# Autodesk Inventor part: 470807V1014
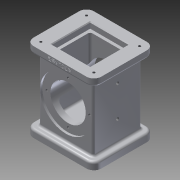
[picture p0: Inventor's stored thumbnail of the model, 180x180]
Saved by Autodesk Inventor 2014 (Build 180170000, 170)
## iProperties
Created: 2017-08
Part Number: 470807V1014
Material: 알루미늄 6061
Document SubType Name: Modeling
Designer: 학생용
Mass: 872.328 g
Surface Area: 642.25 cm^2
Volume: 321.892 cm^3
Density: 2.71 g/cm^3
Appearance: 알루미늄 - 평지
Author: 학생용
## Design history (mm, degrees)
sketch "스케치1"
  geometry: L1 (-36, -41)-(36, -41); L2 (46, -31)-(46, 31); L3 (36, 41)-(-36, 41); L4 (-46, 31)-(-46, -31); L5 (-46, -41)-(46, 41); L6 (46, -41)-(-46, 41); A1 r 10 centre (-36, 31) between (-36, 41) and (-46, 31); A2 r 10 centre (36, 31) between (46, 31) and (36, 41); A3 r 10 centre (36, -31) between (36, -41) and (46, -31); A4 r 10 centre (-36, -31) between (-46, -31) and (-36, -41); 1 further point
  constraints: 12 end point, 8 point on circle, 8 point on line, 8 tangent, 4 centre point, 3 equal radius, 2 midpoint, 2 parallel, 1 horizontal, 1 perpendicular
  dimensions: "d0" = 92 distance of L6.end L5.end; "d1" = 82 distance of L5.end L6.start; "d2" = 10 radius of A1
extrude "돌출1" new body sketch "스케치1" distance "d3" = 10; taper "d4" = 0 deg
node "작업 평면1"
sketch "스케치2"
  geometry: L1 (-36, -41)-(36, -41); L2 (46, -31)-(46, 31); L3 (36, 41)-(-36, 41); L4 (-46, 31)-(-46, -31); L5 (-46, -41)-(46, 41); L6 (46, -41)-(-46, 41); A1 r 10 centre (-36, 31) between (-36, 41) and (-46, 31); A2 r 10 centre (-36, -31) between (-46, -31) and (-36, -41); A3 r 10 centre (36, -31) between (36, -41) and (46, -31); A4 r 10 centre (36, 31) between (46, 31) and (36, 41); 1 further point
  constraints: 12 end point, 8 point on circle, 8 point on line, 8 tangent, 4 centre point, 3 equal radius, 2 midpoint, 2 parallel, 1 horizontal, 1 perpendicular
  dimensions: "d7" = 82 distance of L5.end L6.start; "d8" = 10 radius of A1; "d96" = 92 distance between parallel lines of L2 L4; "d97" = 72 distance of A2.centre A3.centre (derived); "d98" = 62 distance of A4.centre A3.centre (derived)
extrude "돌출2" join sketch "스케치2" distance "d9" = 10; taper "d10" = 0 deg
sketch "스케치3"
  geometry: L1 (-34, -33)-(34, -33); L2 (37, -30)-(37, 30); L3 (34, 33)-(-34, 33); L4 (-37, 30)-(-37, -30); L5 (-37, -33)-(37, 33); L6 (37, -33)-(-37, 33); A1 r 3 centre (-34, 30) between (-34, 33) and (-37, 30); A2 r 3 centre (-34, -30) between (-37, -30) and (-34, -33); A3 r 3 centre (34, -30) between (34, -33) and (37, -30); A4 r 3 centre (34, 30) between (37, 30) and (34, 33); 1 further point
  constraints: 12 end point, 8 point on circle, 8 point on line, 8 tangent, 4 centre point, 3 equal radius, 2 midpoint, 2 parallel, 1 horizontal, 1 perpendicular
  dimensions: "d11" = 74 distance of L6.end L5.end; "d12" = 66 distance of L5.end L6.start; "d31" = 3 radius of A1
extrude "돌출3" join sketch "스케치3" stored distance "d13" = 10; taper "d14" = 0 deg
sketch "스케치4"
  geometry: A1 r 10 centre (36, 31) between (46, 31) and (36, 41) reference; A2 r 10 centre (-36, 31) between (-36, 41) and (-46, 31) reference; A3 r 10 centre (-36, -31) between (-46, -31) and (-36, -41) reference; A4 r 10 centre (36, -31) between (36, -41) and (46, -31) reference; 5 further points
  constraints: 4 coincident
  dimensions: "d15" = 72 distance of point (36, 31) point (-36, 31) (derived); "d16" = 62 distance of point (36, -31) point (36, 31) (derived)
hole "구멍1" sketch "스케치4" at (-36, 31), (36, 31), (36, -31), (-36, -31) diameter "d17" = 3.242; stored, may be unused: countersink angle "d21" = 90 deg, drill point angle "d23" = 118 deg; dims "d18" = 4, "d19" = 4, "d20" = 2, "d22" = 6
sketch "스케치5"
  geometry: A1 r 10 centre (-36, -31) between (-46, -31) and (-36, -41) reference; A2 r 10 centre (36, -31) between (36, -41) and (46, -31) reference; A3 r 10 centre (36, 31) between (46, 31) and (36, 41) reference; A4 r 10 centre (-36, 31) between (-36, 41) and (-46, 31) reference; 5 further points
  constraints: 4 coincident
hole "구멍2" sketch "스케치5" at (36, 31), (36, -31), (-36, -31), (-36, 31) diameter "d24" = 3.242; stored, may be unused: countersink angle "d28" = 90 deg, drill point angle "d30" = 118 deg; dims "d25" = 4, "d26" = 4, "d27" = 2, "d29" = 6
sketch "스케치6"
  geometry: L1 (-21, -24)-(21, -24); L2 (24, -21)-(24, 21); L3 (21, 24)-(-21, 24); L4 (-24, 21)-(-24, -21); L5 (-24, -24)-(24, 24); L6 (24, -24)-(-24, 24); A1 r 3 centre (-21, 21) between (-21, 24) and (-24, 21); A2 r 3 centre (21, -21) between (21, -24) and (24, -21); A3 r 3 centre (21, 21) between (24, 21) and (21, 24); A4 r 3 centre (-21, 21) between (-21, 24) and (-24, 21); A5 r 3 centre (-21, -21) between (-24, -21) and (-21, -24); 3 further points
  constraints: 12 end point, 10 point on circle, 10 point on line, 10 tangent, 5 centre point, 4 equal radius, 3 midpoint, 2 parallel, 2 perpendicular, 1 coincident, 1 horizontal
  dimensions: "d32" = 48 distance of L5.end L6.end; "d33" = 3 radius of A1
extrude "돌출4" cut sketch "스케치6" distance "d34" = 16; taper "d35" = 0 deg
fillet "모깎기2" dims "d37" = 3
sketch "스케치7"
  geometry: L1 (-26, -26)-(26, -26); L2 (26, -26)-(26, 26); L3 (26, 26)-(-26, 26); L4 (-26, 26)-(-26, -26); L5 (-26, -26)-(26, 26); L6 (26, -26)-(-26, 26); 1 further point
  constraints: 12 end point, 2 midpoint, 2 parallel, 2 perpendicular, 1 horizontal
  dimensions: "d38" = 52 distance of L2.end L3.end
extrude "돌출5" cut sketch "스케치7" distance "d39" = 8; taper "d40" = 0 deg
sketch "스케치8"
  geometry: L1 (-19, -22)-(19, -22); L2 (22, -19)-(22, 19); L3 (19, 22)-(-19, 22); L4 (-22, 19)-(-22, -19); L5 (-22, -22)-(22, 22); L6 (22, -22)-(-22, 22); A1 r 3 centre (-19, 19) between (-19, 22) and (-22, 19); A2 r 3 centre (-19, -19) between (-22, -19) and (-19, -22); A3 r 3 centre (19, -19) between (19, -22) and (22, -19); A4 r 3 centre (19, 19) between (22, 19) and (19, 22); 3 further points
  constraints: 12 end point, 8 point on circle, 8 point on line, 8 tangent, 4 centre point, 3 equal radius, 3 midpoint, 2 parallel, 2 perpendicular, 1 coincident, 1 horizontal
  dimensions: "d41" = 44 distance of L5.end L6.end; "d42" = 3 radius of A1
extrude "돌출6" cut sketch "스케치8" distance "d43" = 74; taper "d44" = 0 deg
chamfer "모따기1" distance "d45" = 1; stored, may be unused: second distance "d46" = 2, angle "d47" = 45 deg
sketch "스케치9"
  geometry: L1 (54, 41)-(54, -41); L2 (13, 33)-(95, 33) reference; L3 (98, 36)-(98, 38) reference; L4 (101, 41)-(108, 41) reference; L5 (108, 41)-(108, 27) reference; L6 (108, 27)-(107, 26) reference; L7 (107, 26)-(100, 26) reference; L8 (100, 26)-(100, 22) reference; L9 (100, 22)-(26, 22) reference; L10 (26, 22)-(26, -22) reference; L11 (26, -22)-(100, -22) reference; L12 (100, -22)-(100, -26) reference; L13 (100, -26)-(107, -26) reference; L14 (107, -26)-(108, -27) reference; L15 (108, -27)-(108, -41) reference; L16 (108, -41)-(101, -41) reference; L17 (98, -38)-(98, -36) reference; L18 (95, -33)-(13, -33) reference; L19 (10, -36)-(10, -38) reference; L20 (7, -41)-(0, -41) reference; L21 (0, -41)-(0, -24) reference; L22 (0, -24)-(13, -24) reference; L23 (16, -21)-(16, 21) reference; L24 (13, 24)-(0, 24) reference; L25 (0, 24)-(0, 41) reference; L26 (0, 41)-(7, 41) reference; L27 (10, 38)-(10, 36) reference; L28 (89, -30)-(78, -30); L29 (78, -30)-(78, -22); L30 (78, -22)-(54, -22); L31 (89, -30)-(89, -33); L32 (89, -33)-(54, -33); L33 (54, 22)-(78, 22); L34 (78, 22)-(78, 30); L35 (78, 30)-(89, 30); L36 (89, 30)-(89, 33); L37 (89, 33)-(54, 33); L38 (54, -33)-(54, -22); L39 (54, 22)-(54, 33); L40 (78, -22)-(78, 22); A1 r 3 centre (13, 36) between (10, 36) and (13, 33) reference; A2 r 3 centre (95, 36) between (95, 33) and (98, 36) reference; A3 r 3 centre (101, 38) between (101, 41) and (98, 38) reference; A4 r 3 centre (101, -38) between (98, -38) and (101, -41) reference; A5 r 3 centre (95, -36) between (98, -36) and (95, -33) reference; A6 r 3 centre (13, -36) between (13, -33) and (10, -36) reference; A7 r 3 centre (7, -38) between (7, -41) and (10, -38) reference; A8 r 3 centre (13, -21) between (13, -24) and (16, -21) reference; A9 r 3 centre (13, 21) between (16, 21) and (13, 24) reference; A10 r 3 centre (7, 38) between (10, 38) and (7, 41) reference; 1 further point
  constraints: 28 end point, 7 point on line, 3 perpendicular, 2 horizontal alignment, 2 parallel, 1 collinear, 1 horizontal, 1 midpoint, 1 vertical
  dimensions: "d48" = 54 distance from line of point (0, 0) L1; "d50" = 3 distance of L28.start L31.end; "d51" = 70 diameter of L31 L1; "d52" = 48 diameter of L29 L1; "d53" = 8 distance of L28.end L29.end; "d54" = 3 distance of L35.end L36.end; "d55" = 8 distance of L33.end L34.end; "d56" = 48 diameter of L34 L1; "d57" = 70 diameter of L36 L1
revolve "회전1" sketch "스케치9" stored, may be unused: angle "d58" = 90 deg
sketch "스케치10"
  geometry: C1 r 35 at (0, 0) reference; C2 r 24 at (0, 0) reference; A1 r 29 centre (0, 0) between (0, 29) and (-29, 0); 3 further points
  constraints: 4 point on circle, 2 horizontal alignment, 2 vertical alignment, 1 centre point, 1 coincident
  dimensions: "d59" = 58 diameter of A1
hole "구멍3" sketch "스케치10" at (0, 29), (-29, 0), (0, -29), (29, 0) diameter "d60" = 3.242; stored, may be unused: countersink angle "d64" = 90 deg, drill point angle "d66" = 118 deg; dims "d61" = 4, "d62" = 4, "d63" = 2, "d65" = 6
sketch "스케치11"
  geometry: C1 r 24 at (0, 0) reference; C2 r 35 at (0, 0) reference; A1 r 29 centre (0, 0) between (0, 29) and (-29, 0); 3 further points
  constraints: 4 point on circle, 2 horizontal alignment, 2 vertical alignment, 1 centre point, 1 coincident
  dimensions: "d67" = 58 diameter of A1
hole "구멍4" sketch "스케치11" at (0, 29), (-29, 0), (0, -29), (29, 0) diameter "d68" = 3.242; stored, may be unused: countersink angle "d72" = 90 deg, drill point angle "d74" = 118 deg; dims "d69" = 4, "d70" = 4, "d71" = 2, "d73" = 6
sketch "스케치12"
  geometry: L1 (0, 82)-(60, 82) reference; L2 (-1, -13)-(61, -13) reference; 4 further points
  constraints: 2 vertical alignment, 1 midpoint
  dimensions: "d75" = 38 distance from line of L2 point (30, 25); "d76" = 42 distance of point (30, 67) point (30, 25)
sketch "스케치13"
  geometry: L1 (72, 0)-(0, 0) reference; L2 (-10, 0)-(-10, -7) reference; 2 further points
  constraints: 1 other
  dimensions: "d84" = 4 distance from line of L1 point (36, -4); "d85" = 46 distance from line of L2 point (36, -4)
feature "엠보싱1" sketch "스케치13" dims "d0" = 92, "d1" = 82, "d2" = 10, "d86" = 0.5, "d87" = 0
hole "구멍6" sketch "스케치12" diameter "d88" = 4.134; stored, may be unused: countersink angle "d92" = 90 deg, drill point angle "d94" = 118 deg; dims "d89" = 6, "d90" = 4, "d91" = 2, "d93" = 20
fillet "모깎기3" dims "d95" = 3
node "솔리드1"
node "절단 모서리 투영1"
other parameters: "d5" = -108
